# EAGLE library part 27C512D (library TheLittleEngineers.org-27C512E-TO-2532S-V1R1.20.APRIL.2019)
27C512D Copyright ©07 Jan 2013, by: Robert "The R.A.T." Allen Turner http://www.TheLittleEngineers.org/ TheLittleEngineers@outlook.com OurLittleEngineers@gMail.com You may use these components in your own projects, however, please take note that we CANNOT guarantee the accuracy of these components (nor any part of this library). We make NO guarantees that the components, footprints or schematic symbols in this library are flawless, and we make no promises of fitness for production, prototyping or any other purpose. These libraries are provided for informational purposes only, and are used at your own discretion. By downloading these libraries, you agree that we cannot be held responsible for faulty PCBs. You should always check the footprints with a 1:1 printout. Neither Robert Allen Turner, The Little Engineers, TheLittleEngineers.org, GIMEchip.com, nor anyone affiliated with same shall be held responsible for any outcome resulting from the usage of these files. Should any errors be found, please contact us at one of the above email addresses and we will attempt to repair them. Unless otherwise noted, content of this library is licensed under a Creative Commons Attribution-ShareAlike 4.0 International (CC BY-SA 4.0) license (https://creativecommons.org/licenses/by-sa/4.0/) on 20 April 2019 in memory of my Father, Robert Embry Turner - I LOVE YOU DAD! Rest In Peace. Please note that the GIMEchip.com domain was acquired by Robert "The R.A.T." Allen Turner on December 24, 2018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
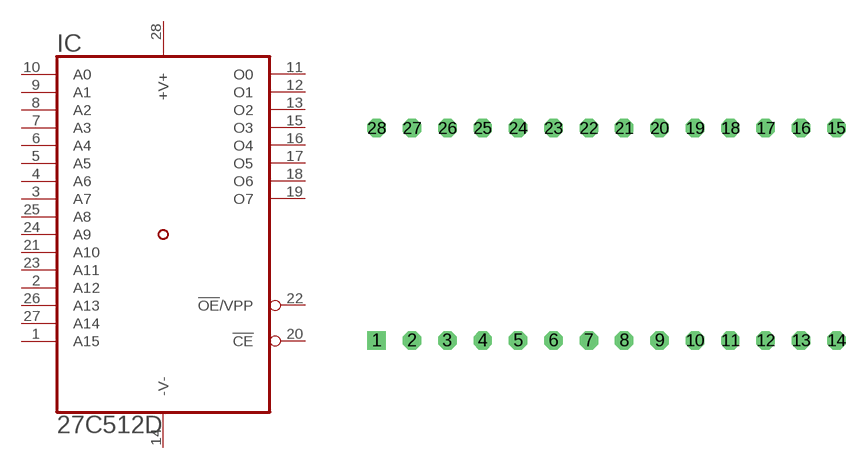
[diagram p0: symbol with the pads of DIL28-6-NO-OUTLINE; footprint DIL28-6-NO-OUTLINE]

Designator prefix IC

## 27C512D-NO  [DIL28-6-NO-OUTLINE]
1  A15  in
2  A12  in
3  A7  in
4  A6  in
5  A5  in
6  A4  in
7  A3  in
8  A2  in
9  A1  in
10  A0  in
11  O0  hiz
12  O1  hiz
13  O2  hiz
14  -V-  pwr
15  O3  hiz
16  O4  hiz
17  O5  hiz
18  O6  hiz
19  O7  hiz
20  !CE  in
21  A10  in
22  !OE!/VPP  in
23  A11  in
24  A9  in
25  A8  in
26  A13  in
27  A14  in
28  +V+  pwr

## Footprint DIL28-6-NO-OUTLINE (pad centres in mm)
Dual In Line Package (DIP) Socket Row Spacing: 0.6 inch (15.24 mm/600 mil) Number of Pins: (Grid): 28 (2 x 14) Pitch: 0.100 inch (2.54mm) Mounting Type: Through Hole Copyright ©07 Jan 2013, by: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
drill 0.813 square: 1 -16.51,-7.62
drill 0.813 octagon: 2 -13.97,-7.62; 3 -11.43,-7.62; 4 -8.89,-7.62; 5 -6.35,-7.62; 6 -3.81,-7.62; 7 -1.27,-7.62; 8 1.27,-7.62; 9 3.81,-7.62; 10 6.35,-7.62; 11 8.89,-7.62; 12 11.43,-7.62; 13 13.97,-7.62; 14 16.51,-7.62; 15 16.51,7.62; 16 13.97,7.62; 17 11.43,7.62; 18 8.89,7.62; 19 6.35,7.62; 20 3.81,7.62; 21 1.27,7.62; 22 -1.27,7.62; 23 -3.81,7.62; 24 -6.35,7.62; 25 -8.89,7.62; 26 -11.43,7.62; 27 -13.97,7.62; 28 -16.51,7.62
